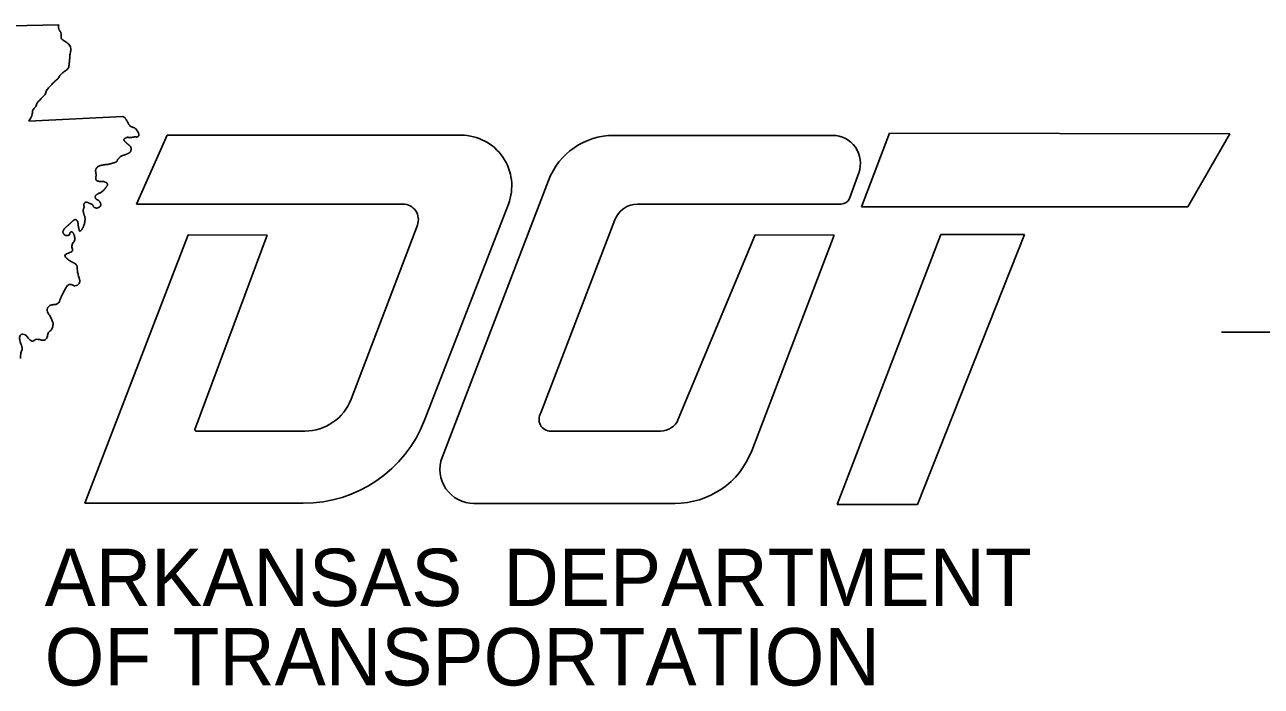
# Model space of a CAD drawing. Extents: x 1096785 to 1382432, y 216169 to 341661.
# Drawn here: x 1186504 to 1188064, y 305234 to 306069 of the extents above; entities that cross this region are included whole.
import ezdxf

# ---------------------------------------------------------------- set-up
doc = ezdxf.new("R2010")
doc.units = 0
doc.layers.add('1', color=7, linetype='Continuous')

msp = doc.modelspace()

# ---------------------------------------------------------------- linework, layer by layer
at = {"layer": '1'}
for p, q in [((1186627.8, 305952.6), (1186509.1, 305946.7)), ((1186683.7, 305929.1), (1186644.8, 305842.3)), ((1187054.6, 305929.2), (1186683.7, 305929.1)), ((1187523.2, 305929), (1187247.3, 305929)), ((1187595.4, 305931.7), (1187559.9, 305838.7)), ((1188024.9, 305930.9), (1187595.4, 305931.7)), ((1187971.8, 305838.7), (1188024.9, 305930.9)), ((1187544.6, 305849.5), (1187556.4, 305881.7)), ((1187164.7, 305872.2), (1187030.7, 305522.6)), ((1186644.8, 305842.3), (1186981.2, 305842.3)), ((1187008.5, 305569.4), (1187114.2, 305842.2)), ((1187277.4, 305842.2), (1187534.4, 305842.3)), ((1187559.9, 305838.7), (1187971.8, 305838.7)), ((1186999.4, 305815.8), (1186915.8, 305595.9)), ((1187155.4, 305578.7), (1187248.6, 305822.4)), ((1186809.7, 305803.2), (1186709.9, 305803.3)), ((1186718.6, 305557.7), (1186809.7, 305803.2)), ((1187425.9, 305803.3), (1187328.7, 305570.7)), ((1187421.3, 305531), (1187525.6, 305803)), ((1187525.6, 305803), (1187425.9, 305803.3)), ((1187660.1, 305803.8), (1187529.3, 305462.9)), ((1187630.7, 305462.9), (1187765.6, 305803.8)), ((1187765.6, 305803.8), (1187660.1, 305803.8)), ((1188014.2, 305680.5), (1191889.2, 305680.5)), ((1186857.5, 305555.7), (1186720, 305555.7)), ((1187306.2, 305555.7), (1187167.9, 305555.6)), ((1187070.7, 305464.5), (1187324.4, 305464.4)), ((1187529.3, 305462.9), (1187630.7, 305462.9))]:
    msp.add_line(p, q, dxfattribs=at)
for points in [[(1186546.7, 306068.6), (1186425.3, 306065.8), (1186163.7, 306061.8), (1185941.8, 306061.3), (1185689.2, 306061.5)], [(1186709.9, 305803.3), (1186579.7, 305464.8), (1186855.2, 305464.6)]]:
    msp.add_lwpolyline(points, dxfattribs=at)
for centre, radius, start, end in [((1187054.6, 305865.3), 63.9, 338.81, 90.0244), ((1187247.3, 305840.5), 88.4, 90.0159, 159.0252), ((1187523.3, 305893.8), 35.2, 339.9797, 90.0159), ((1187534.4, 305853.2), 10.9, 270.0183, 339.9797), ((1186981.2, 305822.7), 19.5, 339.1692, 89.9954), ((1187277.4, 305811.4), 30.8, 90.0183, 159.0781), ((1186857.5, 305618.1), 62.3, 270.0081, 339.1692), ((1186855.4, 305628.8), 164.2, 269.9471, 338.81), ((1187167.8, 305570.5), 14.9, 146.4856, 270.228), ((1187306.2, 305580.1), 24.4, 270.0618, 337.3322), ((1186720, 305557.2), 1.47, 159.6445, 270.0081), ((1187070.7, 305507.3), 42.8, 159.0252, 269.9823), ((1187324.4, 305568.2), 103.8, 269.9823, 339.0187)]:
    msp.add_arc(centre, radius, start, end, dxfattribs=at)
for points in [[(1186509.1, 305946.7), (1186513.3, 305956.2), (1186514.1, 305960.9), (1186517.7, 305965.6), (1186519.6, 305969.9), (1186523.4, 305974.1), (1186526.2, 305977.2), (1186529.7, 305980.7), (1186531.4, 305985.5), (1186534.6, 305989.8), (1186537.9, 305993.3), (1186541.9, 305997.2), (1186546, 306000.9), (1186548.3, 306004.5), (1186551.6, 306007.8), (1186555.2, 306010.5), (1186559, 306014.4), (1186559.9, 306019.3), (1186560.5, 306024.6), (1186560.8, 306030.7), (1186562, 306036.1), (1186561.1, 306041.4), (1186557.1, 306046.1), (1186552.6, 306048.8), (1186549.9, 306051.7), (1186549.6, 306058.2), (1186547.5, 306061.8), (1186546.7, 306068.6)], [(1186541, 305715.5), (1186544.7, 305716.2), (1186548.2, 305720.9), (1186549.8, 305724.9), (1186551.6, 305728.7), (1186553.9, 305733.1), (1186556.2, 305737.4), (1186559.5, 305740.6), (1186563.6, 305740.3), (1186567.2, 305739.1), (1186570.5, 305740.1), (1186573.2, 305744.7), (1186572.6, 305748.7), (1186571.1, 305754.2), (1186570.3, 305758.4), (1186569.4, 305764.7), (1186566.5, 305767.5), (1186561.8, 305770.1), (1186557.1, 305773.6), (1186554.6, 305777.3), (1186559, 305780.5), (1186564, 305783.1), (1186563.4, 305788), (1186564.4, 305792.8), (1186567.2, 305797.7), (1186566.5, 305802.1)], [(1186498.6, 305647.2), (1186499.1, 305654.5), (1186500.5, 305658.8), (1186499, 305665.9), (1186497.5, 305671.3), (1186498.1, 305676.4), (1186501.4, 305678.1), (1186504.6, 305677.1), (1186507.4, 305674.2), (1186510.8, 305670.6), (1186514.1, 305669.4), (1186517.4, 305671.2), (1186520.9, 305671.5), (1186524.9, 305670.7), (1186528.6, 305670.4), (1186530.6, 305671.6), (1186532.5, 305675.4), (1186533.9, 305680.3), (1186536.6, 305682.7), (1186538.7, 305686.6), (1186539.6, 305691.9), (1186538, 305696.1), (1186535.8, 305700.9), (1186533, 305704.9), (1186532.5, 305710.7), (1186535.5, 305714.2), (1186540.5, 305715.4), (1186541, 305715.5)]]:
    msp.add_spline(points, degree=3, dxfattribs=at)
for points in [[(1186636.3, 305926.2), (1186636.7, 305926.2), (1186637.1, 305926.2), (1186637.4, 305926.2), (1186638.2, 305926.4), (1186639, 305926.5), (1186639.8, 305926.6), (1186640.6, 305926.8), (1186641.4, 305926.9), (1186642.2, 305927), (1186642.4, 305927.1), (1186642.6, 305927.1), (1186642.8, 305927.1), (1186643, 305927.1), (1186643.2, 305927.1), (1186643.3, 305927), (1186643.7, 305927), (1186644.1, 305927), (1186644.5, 305926.9), (1186644.8, 305926.9), (1186645.2, 305926.9), (1186645.6, 305927), (1186646, 305927), (1186646.3, 305927.2), (1186646.7, 305927.4), (1186646.7, 305927.4), (1186646.8, 305927.5), (1186646.9, 305927.5), (1186646.9, 305927.6), (1186647, 305927.6), (1186647.1, 305927.7), (1186647.2, 305927.8), (1186647.3, 305927.9), (1186647.4, 305928.1), (1186647.6, 305928.3), (1186647.7, 305928.6), (1186647.8, 305928.9), (1186647.8, 305929.2), (1186647.9, 305929.6), (1186647.9, 305929.9), (1186647.9, 305930.2), (1186647.8, 305930.5), (1186647.7, 305930.8), (1186647.3, 305932.2), (1186646.6, 305933.5), (1186645.8, 305934.7), (1186644.9, 305936.1), (1186644, 305937.3), (1186642.8, 305938.3), (1186642.5, 305938.5), (1186642.2, 305938.7), (1186641.8, 305938.8), (1186641.5, 305938.9), (1186641.1, 305939), (1186640.8, 305939), (1186640.4, 305939.1), (1186640.1, 305939.2), (1186639.7, 305939.2), (1186639.4, 305939.3), (1186639.1, 305939.5), (1186638.8, 305939.6), (1186637.5, 305940.3), (1186636.4, 305941.2), (1186635.5, 305942.3), (1186635.2, 305942.7), (1186635, 305943), (1186634.8, 305943.4), (1186634.6, 305943.8), (1186634.4, 305944.2), (1186634.2, 305944.6), (1186634, 305945), (1186633.8, 305945.4), (1186633.7, 305945.8), (1186633.5, 305946.2), (1186633.2, 305946.6), (1186633, 305947), (1186632.8, 305947.3), (1186632.6, 305947.6), (1186632.5, 305947.9), (1186632.3, 305948.2), (1186632.1, 305948.5), (1186631.9, 305948.7), (1186631.6, 305949.3), (1186631.2, 305949.9), (1186630.8, 305950.5), (1186630.4, 305951), (1186630, 305951.5), (1186629.4, 305951.9), (1186628.9, 305952.3), (1186628.4, 305952.5), (1186627.8, 305952.6)], [(1186622.3, 305899.8), (1186622.3, 305899.9), (1186622.4, 305900), (1186622.5, 305900.1), (1186622.8, 305900.5), (1186623.2, 305900.8), (1186623.5, 305901.2), (1186623.8, 305901.5), (1186624.2, 305901.8), (1186624.6, 305902.1), (1186625, 305902.4), (1186625.4, 305902.7), (1186625.8, 305902.9), (1186626.2, 305903), (1186626.6, 305903.2), (1186627, 305903.4), (1186627.4, 305903.5), (1186627.9, 305903.7), (1186628.3, 305903.8), (1186628.7, 305903.9), (1186629.1, 305904.1), (1186629.5, 305904.2), (1186629.9, 305904.3), (1186630.4, 305904.5), (1186630.8, 305904.6), (1186631.6, 305904.9), (1186632.4, 305905.3), (1186633.2, 305905.6), (1186634.1, 305905.9), (1186634.9, 305906.4), (1186635.7, 305906.9), (1186636, 305907.1), (1186636.3, 305907.4), (1186636.6, 305907.7), (1186636.9, 305908), (1186637.2, 305908.3), (1186637.4, 305908.7), (1186637.8, 305909.4), (1186638.1, 305910.2), (1186638.2, 305910.9), (1186638.3, 305911.3), (1186638.3, 305911.7), (1186638.3, 305912), (1186638.3, 305912.4), (1186638.2, 305912.8), (1186638.1, 305913.1), (1186638, 305913.5), (1186637.8, 305913.9), (1186637.7, 305914.2), (1186637.5, 305914.6), (1186637.3, 305914.9), (1186637, 305915.2), (1186636.6, 305915.6), (1186636.3, 305916), (1186635.9, 305916.3), (1186635.5, 305916.6), (1186635.1, 305916.9), (1186634.8, 305917.2), (1186634.4, 305917.5), (1186634, 305917.8), (1186633.6, 305918.1), (1186633.2, 305918.4), (1186632.8, 305918.8), (1186632.5, 305919.1), (1186631.7, 305919.8), (1186631, 305920.5), (1186630.3, 305921.2), (1186630, 305921.5), (1186629.7, 305921.9), (1186629.5, 305922.3), (1186629.2, 305922.6), (1186629.1, 305922.9), (1186629, 305923.3), (1186629, 305923.4), (1186629, 305923.4), (1186629, 305923.5), (1186629, 305923.6), (1186629, 305923.7), (1186629, 305923.8), (1186629.1, 305923.9), (1186629.2, 305924.1), (1186629.3, 305924.2), (1186629.5, 305924.6), (1186629.8, 305924.8), (1186630.2, 305925.1), (1186630.6, 305925.4), (1186631, 305925.6), (1186631.5, 305925.8), (1186631.9, 305926), (1186632.4, 305926.2), (1186632.8, 305926.4), (1186633, 305926.5), (1186633.2, 305926.5), (1186633.4, 305926.5), (1186633.6, 305926.6), (1186633.8, 305926.6), (1186634, 305926.6), (1186634.4, 305926.5), (1186634.7, 305926.5), (1186635.1, 305926.4), (1186635.5, 305926.4), (1186635.9, 305926.3), (1186636.3, 305926.2), (1186636.3, 305926.2), (1186636.3, 305926.2), (1186636.3, 305926.2)], [(1186593.4, 305874.9), (1186593.4, 305875.2), (1186593.4, 305875.5), (1186593.5, 305875.9), (1186593.6, 305876.4), (1186593.7, 305876.9), (1186593.8, 305877.4), (1186593.9, 305877.9), (1186593.9, 305878.4), (1186593.9, 305878.9), (1186593.9, 305879.4), (1186593.8, 305879.8), (1186593.8, 305880.3), (1186593.7, 305880.8), (1186593.6, 305881.3), (1186593.5, 305881.8), (1186593.5, 305882.2), (1186593.4, 305882.7), (1186593.4, 305883.2), (1186593.3, 305883.7), (1186593.3, 305884.2), (1186593.3, 305884.6), (1186593.3, 305885), (1186593.4, 305885.4), (1186593.4, 305885.8), (1186593.5, 305886.1), (1186593.6, 305886.5), (1186593.8, 305886.8), (1186594.2, 305887.5), (1186594.7, 305888.2), (1186595.3, 305888.7), (1186595.5, 305888.9), (1186595.7, 305889.1), (1186595.9, 305889.2), (1186596.1, 305889.4), (1186596.3, 305889.5), (1186596.5, 305889.6), (1186596.9, 305889.9), (1186597.3, 305890.1), (1186597.7, 305890.3), (1186598.1, 305890.5), (1186598.6, 305890.7), (1186599, 305890.8), (1186599.4, 305890.9), (1186599.9, 305891), (1186600.3, 305891.1), (1186601.1, 305891.3), (1186601.9, 305891.5), (1186602.7, 305891.6), (1186603.6, 305891.8), (1186604.4, 305891.9), (1186605.2, 305892), (1186605.6, 305892.1), (1186605.9, 305892.1), (1186606.3, 305892.1), (1186606.7, 305892.2), (1186607, 305892.2), (1186607.4, 305892.2), (1186607.8, 305892.2), (1186608.2, 305892.3), (1186608.5, 305892.3), (1186608.9, 305892.3), (1186609.3, 305892.4), (1186609.6, 305892.5), (1186610.5, 305892.7), (1186611.3, 305892.9), (1186612.1, 305893.1), (1186613, 305893.4), (1186613.8, 305893.6), (1186614.6, 305893.9), (1186615.4, 305894.1), (1186616.2, 305894.4), (1186617, 305894.6), (1186617.8, 305894.8), (1186618.6, 305895.1), (1186619.4, 305895.5), (1186619.7, 305895.6), (1186620, 305895.8), (1186620.1, 305896.1), (1186620.3, 305896.4), (1186620.5, 305896.8), (1186620.6, 305897.1), (1186620.7, 305897.4), (1186620.8, 305897.8), (1186621, 305898.1), (1186621.1, 305898.5), (1186621.3, 305898.8), (1186621.5, 305899), (1186621.8, 305899.3), (1186622, 305899.6), (1186622.3, 305899.8)], [(1186594.2, 305848.5), (1186594.1, 305848.6), (1186594, 305848.7), (1186593.9, 305848.8), (1186593.4, 305849.2), (1186593.1, 305849.8), (1186592.8, 305850.4), (1186592.5, 305850.9), (1186592.4, 305851.6), (1186592.7, 305852), (1186592.9, 305852.4), (1186593.1, 305852.7), (1186593.4, 305853), (1186593.7, 305853.3), (1186593.9, 305853.6), (1186594.3, 305853.8), (1186594.9, 305854.4), (1186595.6, 305854.9), (1186596.4, 305855.3), (1186596.7, 305855.5), (1186597, 305855.7), (1186597.4, 305855.8), (1186597.7, 305855.9), (1186598.1, 305856), (1186598.4, 305856.1), (1186598.7, 305856.3), (1186599.1, 305856.4), (1186599.4, 305856.5), (1186599.7, 305856.6), (1186600, 305856.8), (1186600.3, 305857), (1186601.7, 305858.1), (1186603, 305859.2), (1186604.1, 305860.5), (1186604.4, 305860.8), (1186604.7, 305861.2), (1186605, 305861.5), (1186605.3, 305861.9), (1186605.6, 305862.2), (1186605.9, 305862.6), (1186606.4, 305863.3), (1186606.9, 305864), (1186607.4, 305864.8), (1186607.8, 305865.3), (1186608, 305865.9), (1186608.2, 305866.5), (1186608.3, 305866.8), (1186608.3, 305867.1), (1186608.3, 305867.4), (1186608.2, 305867.7), (1186608.1, 305868), (1186607.9, 305868.2), (1186607.8, 305868.4), (1186607.7, 305868.6), (1186607.5, 305868.7), (1186607.3, 305868.9), (1186607.2, 305869), (1186607, 305869.1), (1186606.7, 305869.4), (1186606.3, 305869.6), (1186605.9, 305869.8), (1186605.1, 305870.2), (1186604.3, 305870.5), (1186603.5, 305870.6), (1186603.1, 305870.7), (1186602.8, 305870.7), (1186602.4, 305870.7), (1186602, 305870.7), (1186601.6, 305870.7), (1186601.2, 305870.7), (1186600.9, 305870.7), (1186600.5, 305870.7), (1186600.1, 305870.7), (1186599.7, 305870.7), (1186599.3, 305870.7), (1186599, 305870.8), (1186598.5, 305870.8), (1186598, 305870.9), (1186597.5, 305871), (1186597.1, 305871.1), (1186596.6, 305871.2), (1186596.1, 305871.2), (1186595.7, 305871.3), (1186595.2, 305871.5), (1186594.8, 305871.8), (1186594.4, 305872.1), (1186594.1, 305872.4), (1186593.8, 305872.8), (1186593.7, 305873), (1186593.7, 305873.1), (1186593.6, 305873.2), (1186593.6, 305873.3), (1186593.5, 305873.5), (1186593.5, 305873.6), (1186593.4, 305873.8), (1186593.4, 305874.1), (1186593.4, 305874.3), (1186593.3, 305874.5), (1186593.4, 305874.7), (1186593.4, 305874.9)], [(1186577.4, 305834.1), (1186577.4, 305834.3), (1186577.4, 305834.4), (1186577.5, 305834.6), (1186577.6, 305835), (1186577.7, 305835.4), (1186577.8, 305835.8), (1186578, 305836.2), (1186578.2, 305836.6), (1186578.4, 305837.1), (1186578.5, 305837.5), (1186578.6, 305837.9), (1186578.7, 305838.3), (1186578.8, 305838.5), (1186578.8, 305838.6), (1186578.7, 305838.8), (1186578.7, 305839), (1186578.7, 305839.2), (1186578.7, 305839.4), (1186578.6, 305839.8), (1186578.5, 305840.1), (1186578.4, 305840.5), (1186578.3, 305840.9), (1186578.3, 305841.2), (1186578.3, 305841.6), (1186578.3, 305842), (1186578.5, 305842.4), (1186578.7, 305842.7), (1186578.8, 305842.9), (1186578.9, 305843), (1186579.1, 305843.2), (1186579.2, 305843.4), (1186579.3, 305843.5), (1186579.5, 305843.6), (1186579.7, 305843.9), (1186580, 305844.2), (1186580.3, 305844.4), (1186580.6, 305844.6), (1186580.9, 305844.7), (1186581.2, 305844.8), (1186581.5, 305844.9), (1186581.8, 305844.9), (1186582.1, 305844.8), (1186583.1, 305844.3), (1186584.1, 305843.9), (1186585.1, 305843.4), (1186586.2, 305843), (1186587.4, 305842.6), (1186588.5, 305842.1), (1186588.8, 305841.9), (1186589.2, 305841.7), (1186589.4, 305841.3), (1186589.6, 305841), (1186589.8, 305840.6), (1186590, 305840.3), (1186590.2, 305839.9), (1186590.4, 305839.5), (1186590.6, 305839.1), (1186590.8, 305838.7), (1186591.1, 305838.5), (1186591.4, 305838.2), (1186592.1, 305837.7), (1186592.7, 305837.5), (1186593.5, 305837.4), (1186594.2, 305837.2), (1186594.9, 305837.2), (1186595.6, 305837.4), (1186596.3, 305837.6), (1186597, 305837.8), (1186597.6, 305838.2), (1186597.9, 305838.4), (1186598.2, 305838.6), (1186598.5, 305838.8), (1186598.6, 305839), (1186598.8, 305839.1), (1186598.9, 305839.2), (1186599.1, 305839.4), (1186599.2, 305839.5), (1186599.3, 305839.7), (1186600, 305840.6), (1186600, 305842), (1186599.6, 305843), (1186599.1, 305844.3), (1186598.3, 305845.5), (1186597.3, 305846.5), (1186597, 305846.8), (1186596.8, 305847), (1186596.5, 305847.2), (1186596.2, 305847.3), (1186595.9, 305847.5), (1186595.6, 305847.7), (1186595.3, 305847.8), (1186595, 305848), (1186594.7, 305848.1), (1186594.5, 305848.2), (1186594.3, 305848.4), (1186594.2, 305848.5)], [(1186567.5, 305822.7), (1186567.6, 305822.7), (1186567.7, 305822.7), (1186567.7, 305822.6), (1186568.2, 305822.6), (1186568.6, 305822.4), (1186569, 305822.1), (1186569.3, 305821.9), (1186569.5, 305821.7), (1186569.7, 305821.5), (1186569.9, 305821.3), (1186570.1, 305821.1), (1186570.2, 305820.8), (1186570.4, 305820.6), (1186570.5, 305820.3), (1186570.7, 305820.1), (1186570.8, 305819.8), (1186570.9, 305819.5), (1186570.9, 305819.3), (1186571, 305818.9), (1186571, 305818.5), (1186571.1, 305818.1), (1186571.1, 305817.7), (1186571.2, 305817.3), (1186571.2, 305816.9), (1186571.3, 305816.1), (1186571.4, 305815.3), (1186571.5, 305814.5), (1186571.6, 305813.5), (1186571.9, 305812.5), (1186572, 305811.5), (1186572.2, 305810.5), (1186572.5, 305809.5), (1186572.8, 305808.5), (1186572.8, 305808.4), (1186572.9, 305808.3), (1186573, 305808.2), (1186573.1, 305808.2), (1186573.2, 305808.1), (1186573.3, 305808.2), (1186573.6, 305808.2), (1186573.9, 305808.4), (1186574.2, 305808.6), (1186574.9, 305809.1), (1186575.5, 305809.5), (1186575.9, 305810.2), (1186576.2, 305810.6), (1186576.4, 305811.1), (1186576.7, 305811.5), (1186576.9, 305812), (1186577.2, 305812.4), (1186577.4, 305812.9), (1186577.6, 305813.3), (1186577.8, 305813.8), (1186578, 305814.3), (1186578.2, 305814.7), (1186578.4, 305815.2), (1186578.5, 305815.7), (1186579.1, 305817.5), (1186579.5, 305819.3), (1186579.8, 305821.1), (1186580, 305822.4), (1186580.2, 305823.7), (1186579.9, 305824.9), (1186579.5, 305826.5), (1186579, 305828.1), (1186578.5, 305829.8), (1186578.2, 305831), (1186577.8, 305832.2), (1186577.5, 305833.4), (1186577.4, 305833.6), (1186577.4, 305833.9), (1186577.4, 305834.1)], [(1186566.5, 305802.1), (1186566.2, 305803), (1186565.9, 305803.9), (1186565.5, 305804.7), (1186565.3, 305805.1), (1186565.1, 305805.5), (1186564.8, 305805.9), (1186564.7, 305806.1), (1186564.5, 305806.3), (1186564.4, 305806.5), (1186564.3, 305806.7), (1186564.1, 305806.8), (1186564, 305807), (1186563.8, 305807.2), (1186563.6, 305807.3), (1186563.4, 305807.3), (1186563.2, 305807.4), (1186562.9, 305807.3), (1186562.7, 305807.3), (1186562.4, 305807.2), (1186562.2, 305807.1), (1186561.9, 305807), (1186561.7, 305806.9), (1186561.5, 305806.8), (1186561.3, 305806.6), (1186561.1, 305806.4), (1186561, 305806.1), (1186560.9, 305805.8), (1186560.8, 305805.6), (1186560.8, 305805.2), (1186560.7, 305805), (1186560.7, 305804.7), (1186560.6, 305804.4), (1186560.5, 305804.1), (1186560.4, 305803.8), (1186560.2, 305803.5), (1186560, 305803.4), (1186559.8, 305803.2), (1186559.5, 305803.1), (1186559.3, 305803), (1186559.1, 305802.9), (1186558.9, 305802.8), (1186558.6, 305802.7), (1186558.4, 305802.6), (1186558.2, 305802.5), (1186558, 305802.5), (1186557.8, 305802.4), (1186557.5, 305802.4), (1186557.3, 305802.4), (1186557, 305802.4), (1186556.7, 305802.4), (1186556.4, 305802.4), (1186556.2, 305802.5), (1186555.9, 305802.5), (1186555.6, 305802.6), (1186555.3, 305802.7), (1186555, 305802.8), (1186554.7, 305803), (1186554.4, 305803.2), (1186554.1, 305803.4), (1186553.8, 305803.6), (1186553.7, 305803.7), (1186553.7, 305803.8), (1186553.6, 305803.9), (1186553.5, 305804), (1186553.4, 305804.1), (1186553.3, 305804.2), (1186553.1, 305804.4), (1186553, 305804.6), (1186552.8, 305804.8), (1186552.6, 305805.2), (1186552.4, 305805.6), (1186552.3, 305806.1), (1186552.1, 305806.5), (1186552.1, 305806.9), (1186552.1, 305807.3), (1186552.1, 305807.7), (1186552.2, 305808.1), (1186552.3, 305808.5), (1186552.5, 305808.9), (1186552.7, 305809.2), (1186552.8, 305809.6), (1186553, 305809.9), (1186553.2, 305810.3), (1186553.5, 305810.6), (1186554, 305811.3), (1186554.5, 305812), (1186555.1, 305812.5), (1186555.5, 305812.9), (1186555.8, 305813.2), (1186556.2, 305813.5), (1186556.6, 305813.8), (1186557, 305814.1), (1186557.4, 305814.4), (1186557.8, 305814.7), (1186558.1, 305815.1), (1186558.5, 305815.4), (1186558.9, 305815.7), (1186559.3, 305816), (1186559.6, 305816.3), (1186560.2, 305816.9), (1186560.8, 305817.5), (1186561.4, 305818.1), (1186562, 305818.7), (1186562.7, 305819.3), (1186563.3, 305819.9), (1186563.8, 305820.4), (1186564.3, 305820.8), (1186564.8, 305821.2), (1186565.1, 305821.4), (1186565.4, 305821.6), (1186565.6, 305821.8), (1186565.9, 305822), (1186566.2, 305822.2), (1186566.5, 305822.4), (1186566.8, 305822.6), (1186567.1, 305822.7), (1186567.5, 305822.7)]]:
    msp.add_open_spline(points, degree=3, dxfattribs=at)

# ---------------------------------------------------------------- texts
for s, height, p in [('ARKANSAS', 72.38, (1186529, 305334.9)), ('DEPARTMENT', 72.38, (1187108, 305334.9)), ('OF TRANSPORTATION', 72.383, (1186529, 305234.7))]:
    msp.add_text(s, height=height, dxfattribs=at).set_placement(p)

doc.saveas('drawing.dxf')
